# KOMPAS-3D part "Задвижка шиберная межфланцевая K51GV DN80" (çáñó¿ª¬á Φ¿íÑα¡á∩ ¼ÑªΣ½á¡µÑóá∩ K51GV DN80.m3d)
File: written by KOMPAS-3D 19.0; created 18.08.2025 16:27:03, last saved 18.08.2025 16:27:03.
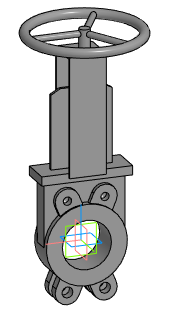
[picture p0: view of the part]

Document properties: Автор: Евгений; Полное имя файла: E:\Dendor Работа Сачек\3D для проектировщиков\2.4 Тип K51GV. Задвижка шиберная межфланцевая\stp_Задвижка шиберная K51GV DN50-400 с маховиком\Задвижка шиберная межфланцевая K51GV DN80.m3d

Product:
- Part/product: Задвижка шиберная межфланцевая K51GV DN80

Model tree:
1. Операция без истории:1  (labels: Задвижка шиберная межфланцевая K51GV DN80)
